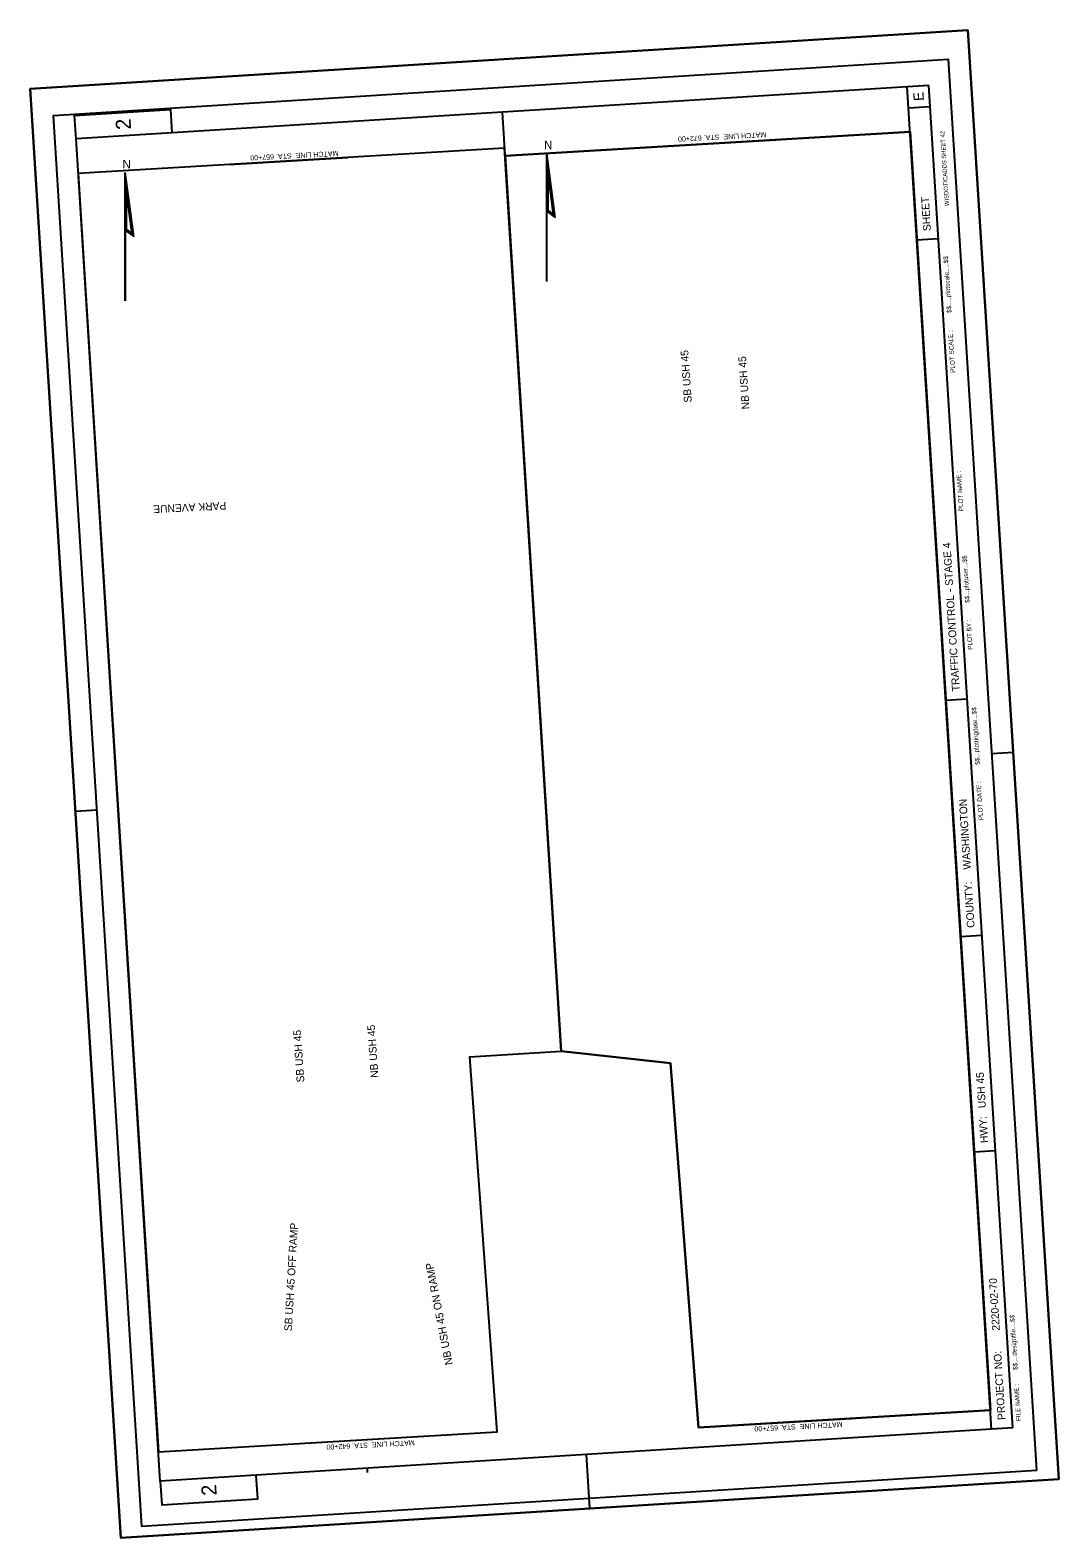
# Model space of a CAD drawing. Extents: x 355165 to 356369, y 186284 to 188050.
import ezdxf

# ---------------------------------------------------------------- set-up
doc = ezdxf.new("R2010")
doc.units = 0
for name, color, linetype in [('Default', 7, 'Continuous'), ('P_ALI_20', 7, 'Continuous'), ('P_ALI_20_PIData', 7, 'Continuous'), ('P_ALI_20_Sta', 7, 'Continuous'), ('P_ALI_20_Tic', 7, 'Continuous'), ('P_ALI_50_Equation', 7, 'Continuous'), ('P_ALI_50_PIData', 7, 'Continuous'), ('P_ALI_50_Sta', 7, 'Continuous'), ('P_ALI_50_Tic', 7, 'Continuous')]:
    doc.layers.add(name, color=color, linetype=linetype)

msp = doc.modelspace()

# ---------------------------------------------------------------- linework, layer by layer
at = {"layer": 'Default'}
for points in [[(355786.9, 186854.2), (355914.8, 186840), (355947.6, 186413.3), (356289.2, 186433.5), (356195.3, 187930.6), (355721.2, 187902.6)], [(355315.3, 186385), (355711.9, 186408.4), (355679.7, 186847.5), (355786.9, 186854.2), (355720.6, 187911.5), (355221.5, 187882)], [(355315.3, 186385), (355711.9, 186408.4), (355679.7, 186847.5), (355786.9, 186854.2), (355720.6, 187911.5), (355221.5, 187882)], [(355315.3, 186385), (355711.9, 186408.4), (355679.7, 186847.5), (355786.9, 186854.2), (355720.6, 187911.5), (355221.5, 187882)]]:
    msp.add_lwpolyline(points, close=True, dxfattribs=at)
at = {"layer": 'P_ALI_20'}
msp.add_lwpolyline([(355271.5, 186284.2), (355165.2, 187980.9), (356263, 188049.7), (356369.4, 186353), (355271.5, 186284.2)], dxfattribs=at)
at = {"layer": 'P_ALI_20_PIData'}
for p, q in [((355779.9, 187830.2), (355769.9, 187905.2)), ((355769.9, 187837.7), (355769.9, 187905.2)), ((355770.6, 187838.1), (355770.6, 187893.9)), ((355778.9, 187831.9), (355770.6, 187893.9)), ((355286.4, 187807.9), (355276.4, 187882.9)), ((355276.4, 187815.4), (355276.4, 187882.9)), ((355277.2, 187815.7), (355277.2, 187871.6)), ((355285.4, 187809.5), (355277.2, 187871.6)), ((355771.4, 187838.5), (355771.4, 187882.6)), ((355777.9, 187833.6), (355771.4, 187882.6)), ((355277.9, 187816.1), (355277.9, 187860.3)), ((355284.5, 187811.2), (355277.9, 187860.3)), ((355769.9, 187837.7), (355779.9, 187830.2)), ((355769.9, 187755.2), (355769.9, 187837.7)), ((355770.1, 187755.2), (355770.1, 187837.5)), ((355770.6, 187838.1), (355778.9, 187831.9)), ((355771.4, 187838.5), (355777.9, 187833.6)), ((355276.4, 187815.4), (355286.4, 187807.9)), ((355276.4, 187732.9), (355276.4, 187815.4)), ((355276.7, 187732.9), (355276.7, 187815.2)), ((355277.2, 187815.7), (355285.4, 187809.5)), ((355277.9, 187816.1), (355284.5, 187811.2))]:
    msp.add_line(p, q, dxfattribs=at)
for points in [[(355769.9, 187905.1), (355769.9, 187905.1)], [(355276.4, 187882.8), (355276.4, 187882.8)]]:
    msp.add_lwpolyline(points, dxfattribs=at)
at = {"layer": 'P_ALI_20_Sta'}
msp.add_lwpolyline([(355947.6, 186413.3), (355914.8, 186840), (355786.9, 186854.2), (355721.2, 187902.6), (355721.2, 187902.6), (356195.3, 187930.6), (356195.3, 187930.6), (356289.2, 186433.5), (356289.2, 186433.5)], close=True, dxfattribs=at)
at = {"layer": 'P_ALI_20_Tic'}
msp.add_lwpolyline([(355271.5, 186284.2), (355165.2, 187980.9), (356263, 188049.7), (356369.4, 186353)], close=True, dxfattribs=at)
at = {"layer": 'P_ALI_50_Equation'}
for p, q in [((355898.9, 187913.1), (356037.9, 187921.3)), ((355398.1, 187892.5), (355537.2, 187900.7)), ((355987.4, 186415.7), (356126.5, 186423.9)), ((355486.6, 186395.1), (355625.6, 186403.3))]:
    msp.add_line(p, q, dxfattribs=at)
at = {"layer": 'P_ALI_50_Sta'}
for points in [[(356369.4, 186353), (356263, 188049.7), (355165.2, 187980.9), (355271.5, 186284.2)], [(356343.7, 186363.4), (356240.1, 188015.2), (355192.2, 187949.5), (355295.7, 186297.7)]]:
    msp.add_lwpolyline(points, close=True, dxfattribs=at)
at = {"layer": 'P_ALI_50_Tic'}
for p, q in [((356263, 188049.7), (356213.1, 188046.5)), ((356266.1, 187999.8), (356263, 188049.7)), ((355215.1, 187984), (355165.2, 187980.9)), ((355168.3, 187931), (355165.2, 187980.9)), ((356217, 187984.9), (355218.9, 187922.4)), ((356290.6, 186411.4), (356192, 187983.3)), ((356315.5, 186413), (356217, 187984.9)), ((356218.5, 187960), (356193.6, 187958.4)), ((355786.9, 186854.2), (355718, 187953.6)), ((355317.5, 186350.4), (355218.9, 187922.4)), ((356228.2, 187805.3), (356203.3, 187803.7)), ((356262, 187266.3), (356237.1, 187264.8)), ((356317.6, 187178.9), (356314.5, 187228.8)), ((356316, 187203.8), (356291.1, 187202.3)), ((355219.8, 187110.1), (355216.6, 187160)), ((355218.2, 187135), (355243.1, 187136.6)), ((356279.4, 186989.4), (356254.4, 186987.8)), ((356295.2, 186737.4), (356270.2, 186735.8)), ((355814.1, 186419.1), (355814.1, 186419.1)), ((356315.5, 186413), (355317.5, 186350.4)), ((356369.4, 186353), (356366.2, 186402.9)), ((355559.5, 186365.6), (355559.8, 186360.6)), ((355820.5, 186318.6), (355816.5, 186381.7)), ((356369.4, 186353), (356319.5, 186349.9)), ((355271.5, 186284.2), (355268.4, 186334.1)), ((355845.4, 186320.2), (355795.5, 186317)), ((355321.4, 186287.3), (355271.5, 186284.2))]:
    msp.add_line(p, q, dxfattribs=at)
for points in [[(355218.9, 187922.4), (355217.2, 187949.8), (355329.5, 187956.8), (355331.2, 187929.4)], [(355317.5, 186350.4), (355319.2, 186323), (355431.5, 186330), (355429.8, 186357.5)]]:
    msp.add_lwpolyline(points, close=True, dxfattribs=at)

# ---------------------------------------------------------------- texts
at = {"layer": 'P_ALI_20_PIData'}
for p in [(355766.8, 187910.2), (355273.3, 187887.8)]:
    msp.add_text('N', height=10, dxfattribs=at).set_placement(p)
at = {"layer": 'P_ALI_50_PIData'}
for s, height, rotation, p in [('MATCH LINE  STA. 672+00', 6, 182.9694, (356026.6, 187930.3)), ('MATCH LINE  STA. 657+00', 6, 182.9694, (355525.9, 187908.4)), ('SB USH 45', 9, 93.9038, (355939.7, 187613.9)), ('NB USH 45', 9, 93.9038, (356007.3, 187606)), ('PARK AVENUE', 9, 182.8915, (355394.5, 187497.4)), ('SB USH 45', 9, 93.9038, (355486.2, 186817.8)), ('NB USH 45', 9, 93.9038, (355572.9, 186823.2)), ('SB USH 45 OFF RAMP', 9, 86.7169, (355471.5, 186526)), ('NB USH 45 ON RAMP', 9, 101.0477, (355660, 186487.5)), ('MATCH LINE  STA. 657+00', 6, 182.9694, (356116, 186420)), ('MATCH LINE  STA. 642+00', 6, 182.9694, (355615.2, 186398.6))]:
    msp.add_text(s, height=height, rotation=rotation, dxfattribs=at).set_placement(p)
at = {"layer": 'P_ALI_50_Tic'}
for s, height, p in [('E', 12, (356211.5, 187967.1)), ('2', 17.5, (355283.4, 187933.6)), ('WISDOT/CADDS SHEET 42', 5, (356240.9, 187843.8)), ('SHEET ', 9, (356219.6, 187814.7)), ('$$.....plotscale.....$$', 5.4, (356243.7, 187718.6)), ('PLOT SCALE : ', 5.4, (356248.1, 187648.5)), ('PLOT NAME :                      ', 5.4, (356257.7, 187486.5)), ('TRAFFIC CONTROL - STAGE 4', 9, (356253.4, 187275.8)), ('$$...plotuser...$$', 5.4, (356265, 187379.2)), ('PLOT BY :', 5.4, (356268.4, 187324.3)), ('$$...plottingdate...$$', 5.4, (356276.9, 187189.6)), ('PLOT DATE :', 5.4, (356280.9, 187124.7)), (' WASHINGTON', 9, (356266.7, 187063.7)), ('COUNTY:', 9, (356270.8, 186998.8)), (' USH 45', 9, (356284.2, 186784.3)), ('HWY:', 9, (356286.6, 186746.8)), (' 2220-02-70', 9, (356300.6, 186523.8)), ('$$....designfile....$$', 5.4, (356321.3, 186481)), ('PROJECT NO:', 9, (356306.9, 186422.5)), ('FILE NAME :', 5.4, (356325, 186421.1)), ('2', 17.5, (355383.6, 186334.2))]:
    msp.add_text(s, height=height, rotation=93.5868, dxfattribs=at).set_placement(p)

doc.saveas('drawing.dxf')
